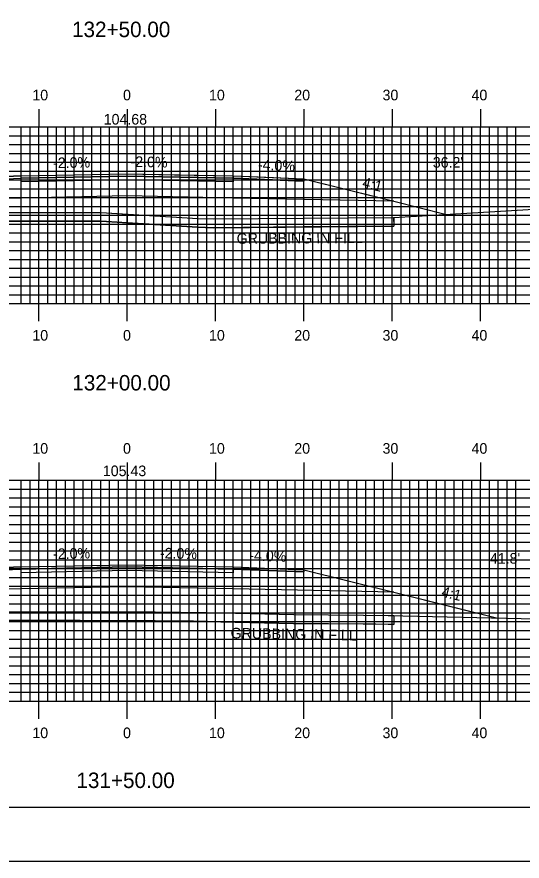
# Model space of a CAD drawing. Extents: x 1774383 to 1774727, y 442591 to 442811.
# Drawn here: x 1774536.7 to 1774593.9, y 442590.5 to 442686.1 of the extents above; entities that cross this region are included whole.
import ezdxf

# ---------------------------------------------------------------- set-up
doc = ezdxf.new("R2010")
doc.units = 0
for name, color, linetype in [('ANNOTATION', 7, 'Continuous'), ('BORDER', 7, 'Continuous'), ('D_Roadway_Centerline', 7, 'Continuous'), ('D_Roadway_Centerline_Text', 7, 'Continuous'), ('D_Roadway_Edge_Shoulder', 7, 'Continuous'), ('D_Roadway_Edge_TW', 7, 'Continuous'), ('D_Roadway_Pavement', 7, 'Continuous'), ('D_Roadway_SlopeLines', 7, 'Continuous'), ('D_Roadway_SubGrade', 7, 'Continuous'), ('D_Text_Standard', 7, 'Continuous'), ('GRUBBING IN FILL', 7, 'Continuous'), ('H_V ANNOTATION', 7, 'Continuous'), ('MAJOR', 7, 'Continuous'), ('MINOR', 7, 'Continuous'), ('PLOT BOUNDARY', 7, 'Continuous'), ('S_Roadway_Centerline', 7, 'Continuous')]:
    doc.layers.add(name, color=color, linetype=linetype)

msp = doc.modelspace()

# ---------------------------------------------------------------- linework, layer by layer
at = {"layer": 'BORDER'}
msp.add_lwpolyline([(1774399.572, 442596.665), (1774719.572, 442596.665), (1774719.572, 442806.665), (1774399.572, 442806.665)], close=True, dxfattribs=at)
at = {"layer": 'D_Roadway_Centerline'}
for points in [[(1774512.297, 442663.565), (1774517.172, 442664.784), (1774517.278, 442664.811), (1774518.998, 442665.24), (1774523.443, 442666.352), (1774529.172, 442667.784), (1774537.172, 442668.104), (1774549.172, 442668.344), (1774554.507, 442668.238), (1774561.172, 442668.104), (1774563.119, 442668.026), (1774569.172, 442667.784), (1774577.691, 442665.654), (1774579.346, 442665.24), (1774585.327, 442663.745)], [(1774511.278, 442619.06), (1774517.172, 442620.534), (1774517.836, 442620.7), (1774518.998, 442620.99), (1774522.93, 442621.973), (1774529.172, 442623.534), (1774537.172, 442623.854), (1774549.172, 442624.094), (1774561.173, 442623.854), (1774569.172, 442623.534), (1774579.346, 442620.99), (1774585.953, 442619.339), (1774590.971, 442618.084)]]:
    msp.add_lwpolyline(points, dxfattribs=at)
at = {"layer": 'D_Roadway_Edge_Shoulder'}
for points in [[(1774537.172, 442668.104), (1774529.172, 442667.784), (1774529.172, 442667.534), (1774537.172, 442667.854)], [(1774561.172, 442668.104), (1774569.172, 442667.784), (1774569.172, 442667.534), (1774561.172, 442667.854)], [(1774537.172, 442623.854), (1774529.172, 442623.534), (1774529.172, 442623.284), (1774537.172, 442623.604)], [(1774561.173, 442623.854), (1774569.172, 442623.534), (1774569.172, 442623.284), (1774561.173, 442623.604)]]:
    msp.add_lwpolyline(points, close=True, dxfattribs=at)
at = {"layer": 'D_Roadway_Edge_TW'}
for points in [[(1774537.172, 442667.854), (1774537.172, 442668.104), (1774549.172, 442668.344), (1774561.172, 442668.104), (1774561.172, 442667.854), (1774549.172, 442668.094)], [(1774537.172, 442623.604), (1774537.172, 442623.854), (1774549.172, 442624.094), (1774561.173, 442623.854), (1774561.173, 442623.604), (1774549.172, 442623.844)]]:
    msp.add_lwpolyline(points, close=True, dxfattribs=at)
at = {"layer": 'D_Roadway_Pavement'}
for points in [[(1774537.172, 442667.437), (1774537.172, 442667.854), (1774549.172, 442668.094), (1774561.172, 442667.854), (1774561.172, 442667.437), (1774549.172, 442667.677)], [(1774537.172, 442623.187), (1774537.172, 442623.604), (1774549.172, 442623.844), (1774561.173, 442623.604), (1774561.173, 442623.187), (1774549.172, 442623.427)]]:
    msp.add_lwpolyline(points, close=True, dxfattribs=at)
at = {"layer": 'D_Roadway_SlopeLines'}
for points in [[(1774569.172, 442667.784), (1774579.346, 442665.24), (1774585.327, 442663.745)], [(1774569.172, 442623.534), (1774579.346, 442620.99), (1774590.971, 442618.084)]]:
    msp.add_lwpolyline(points, dxfattribs=at)
at = {"layer": 'D_Roadway_SubGrade'}
for points in [[(1774537.172, 442665.604), (1774518.998, 442665.24), (1774529.172, 442667.784), (1774529.172, 442667.534), (1774537.172, 442667.854), (1774549.172, 442668.094), (1774561.172, 442667.854), (1774569.172, 442667.534), (1774569.172, 442667.784), (1774579.346, 442665.24), (1774561.172, 442665.604), (1774549.172, 442665.844)], [(1774537.172, 442621.354), (1774518.998, 442620.99), (1774529.172, 442623.534), (1774529.172, 442623.284), (1774537.172, 442623.604), (1774549.172, 442623.844), (1774561.173, 442623.604), (1774569.172, 442623.284), (1774569.172, 442623.534), (1774579.346, 442620.99), (1774561.173, 442621.354), (1774549.172, 442621.594)]]:
    msp.add_lwpolyline(points, close=True, dxfattribs=at)
at = {"layer": 'GRUBBING IN FILL'}
for p, q in [((1774579.346, 442663.423), (1774579.346, 442662.421)), ((1774579.346, 442663.423), (1774579.346, 442662.421)), ((1774579.346, 442618.349), (1774579.346, 442617.348)), ((1774579.346, 442618.349), (1774579.346, 442617.348))]:
    msp.add_line(p, q, dxfattribs=at)
for points in [[(1774518.998, 442663.701), (1774522.021, 442663.762), (1774532.978, 442663.985), (1774539.889, 442663.982), (1774546.228, 442663.979), (1774549.172, 442663.793), (1774549.172, 442662.791), (1774546.196, 442662.979), (1774539.876, 442662.982), (1774533.555, 442662.984), (1774525.99, 442662.843), (1774518.998, 442662.701)], [(1774518.998, 442663.701), (1774522.021, 442663.762), (1774532.978, 442663.985), (1774539.889, 442663.982), (1774546.228, 442663.979), (1774549.172, 442663.793), (1774549.172, 442662.791), (1774546.196, 442662.979), (1774539.876, 442662.982), (1774533.555, 442662.984), (1774525.99, 442662.843), (1774518.998, 442662.701)], [(1774549.172, 442663.793), (1774551.687, 442663.634), (1774557.147, 442663.289), (1774558.926, 442663.249), (1774569.111, 442663.335), (1774579.296, 442663.421), (1774579.346, 442662.421), (1774569.132, 442662.335), (1774558.919, 442662.249), (1774557.104, 442662.29), (1774551.65, 442662.635), (1774549.172, 442662.791)], [(1774549.172, 442663.793), (1774551.687, 442663.634), (1774557.147, 442663.289), (1774558.926, 442663.249), (1774569.111, 442663.335), (1774579.296, 442663.421), (1774579.346, 442662.421), (1774569.132, 442662.335), (1774558.919, 442662.249), (1774557.104, 442662.29), (1774551.65, 442662.635), (1774549.172, 442662.791)], [(1774518.998, 442619.027), (1774521.621, 442618.997), (1774530.184, 442618.901), (1774535.375, 442618.788), (1774543.86, 442618.773), (1774549.172, 442618.764), (1774549.172, 442617.764), (1774543.852, 442617.773), (1774535.364, 442617.788), (1774530.168, 442617.901), (1774524.583, 442617.964), (1774518.998, 442618.026)], [(1774518.998, 442619.027), (1774521.621, 442618.997), (1774530.184, 442618.901), (1774535.375, 442618.788), (1774543.86, 442618.773), (1774549.172, 442618.764), (1774549.172, 442617.764), (1774543.852, 442617.773), (1774535.364, 442617.788), (1774530.168, 442617.901), (1774524.583, 442617.964), (1774518.998, 442618.026)], [(1774549.172, 442618.764), (1774552.345, 442618.759), (1774556.689, 442618.702), (1774558.135, 442618.672), (1774563.076, 442618.561), (1774568.018, 442618.449), (1774571.958, 442618.419), (1774575.898, 442618.39), (1774578.717, 442618.363), (1774579.346, 442618.349), (1774579.346, 442617.348), (1774577.295, 442617.376), (1774571.946, 442617.419), (1774568.003, 442617.449), (1774563.058, 442617.561), (1774556.671, 442617.702), (1774552.34, 442617.759), (1774549.172, 442617.764)], [(1774549.172, 442618.764), (1774552.345, 442618.759), (1774556.689, 442618.702), (1774558.135, 442618.672), (1774563.076, 442618.561), (1774568.018, 442618.449), (1774571.958, 442618.419), (1774575.898, 442618.39), (1774578.717, 442618.363), (1774579.346, 442618.349), (1774579.346, 442617.348), (1774577.295, 442617.376), (1774571.946, 442617.419), (1774568.003, 442617.449), (1774563.058, 442617.561), (1774556.671, 442617.702), (1774552.34, 442617.759), (1774549.172, 442617.764)]]:
    msp.add_lwpolyline(points, close=True, dxfattribs=at)
for points in [[(1774518.998, 442662.701), (1774532.981, 442662.985), (1774533.233, 442662.981), (1774533.555, 442662.984), (1774546.196, 442662.979), (1774557.104, 442662.29), (1774558.919, 442662.249), (1774579.346, 442662.421)], [(1774518.998, 442662.701), (1774532.981, 442662.985), (1774533.233, 442662.981), (1774533.555, 442662.984), (1774546.196, 442662.979), (1774557.104, 442662.29), (1774558.919, 442662.249), (1774579.346, 442662.421)], [(1774518.998, 442618.026), (1774530.168, 442617.901), (1774535.364, 442617.788), (1774552.34, 442617.759), (1774555.229, 442617.732), (1774558.114, 442617.672), (1774568.003, 442617.449), (1774575.889, 442617.39), (1774578.7, 442617.363), (1774579.346, 442617.348)], [(1774518.998, 442618.026), (1774530.168, 442617.901), (1774535.364, 442617.788), (1774552.34, 442617.759), (1774555.229, 442617.732), (1774558.114, 442617.672), (1774568.003, 442617.449), (1774575.889, 442617.39), (1774578.7, 442617.363), (1774579.346, 442617.348)]]:
    msp.add_lwpolyline(points, dxfattribs=at)
at = {"layer": 'MAJOR'}
for p, q in [((1774539.172, 442675.669), (1774539.172, 442673.665)), ((1774549.172, 442675.669), (1774549.172, 442673.665)), ((1774559.172, 442675.669), (1774559.172, 442673.665)), ((1774569.172, 442675.669), (1774569.172, 442673.665)), ((1774579.172, 442675.669), (1774579.172, 442673.665)), ((1774589.172, 442675.669), (1774589.172, 442673.665)), ((1774409.172, 442673.665), (1774689.172, 442673.665)), ((1774409.172, 442673.665), (1774689.172, 442673.665)), ((1774539.172, 442653.665), (1774539.172, 442673.665)), ((1774549.172, 442653.665), (1774549.172, 442673.665)), ((1774559.172, 442653.665), (1774559.172, 442673.665)), ((1774569.172, 442653.665), (1774569.172, 442673.665)), ((1774579.172, 442653.665), (1774579.172, 442673.665)), ((1774589.172, 442653.665), (1774589.172, 442673.665)), ((1774409.172, 442668.665), (1774689.172, 442668.665)), ((1774409.172, 442663.665), (1774689.172, 442663.665)), ((1774409.172, 442658.665), (1774689.172, 442658.665)), ((1774409.172, 442653.665), (1774689.172, 442653.665)), ((1774409.172, 442653.665), (1774689.172, 442653.665)), ((1774539.172, 442651.661), (1774539.172, 442653.665)), ((1774549.172, 442651.661), (1774549.172, 442653.665)), ((1774559.172, 442651.661), (1774559.172, 442653.665)), ((1774569.172, 442651.661), (1774569.172, 442653.665)), ((1774579.172, 442651.661), (1774579.172, 442653.665)), ((1774589.172, 442651.661), (1774589.172, 442653.665)), ((1774539.172, 442635.669), (1774539.172, 442633.665)), ((1774549.172, 442635.669), (1774549.172, 442633.665)), ((1774559.172, 442635.669), (1774559.172, 442633.665)), ((1774569.172, 442635.669), (1774569.172, 442633.665)), ((1774579.172, 442635.669), (1774579.172, 442633.665)), ((1774589.172, 442635.669), (1774589.172, 442633.665)), ((1774409.172, 442633.665), (1774689.172, 442633.665)), ((1774409.172, 442633.665), (1774689.172, 442633.665)), ((1774539.172, 442608.665), (1774539.172, 442633.665)), ((1774549.172, 442608.665), (1774549.172, 442633.665)), ((1774559.172, 442608.665), (1774559.172, 442633.665)), ((1774569.172, 442608.665), (1774569.172, 442633.665)), ((1774579.172, 442608.665), (1774579.172, 442633.665)), ((1774589.172, 442608.665), (1774589.172, 442633.665)), ((1774409.172, 442628.665), (1774689.172, 442628.665)), ((1774409.172, 442623.665), (1774689.172, 442623.665)), ((1774409.172, 442618.665), (1774689.172, 442618.665)), ((1774409.172, 442613.665), (1774689.172, 442613.665)), ((1774409.172, 442608.665), (1774689.172, 442608.665)), ((1774409.172, 442608.665), (1774689.172, 442608.665)), ((1774539.172, 442606.661), (1774539.172, 442608.665)), ((1774549.172, 442606.661), (1774549.172, 442608.665)), ((1774559.172, 442606.661), (1774559.172, 442608.665)), ((1774569.172, 442606.661), (1774569.172, 442608.665)), ((1774579.172, 442606.661), (1774579.172, 442608.665)), ((1774589.172, 442606.661), (1774589.172, 442608.665))]:
    msp.add_line(p, q, dxfattribs=at)
at = {"layer": 'MINOR'}
for p, q in [((1774537.172, 442653.665), (1774537.172, 442673.665)), ((1774538.172, 442653.665), (1774538.172, 442673.665)), ((1774540.172, 442653.665), (1774540.172, 442673.665)), ((1774541.172, 442653.665), (1774541.172, 442673.665)), ((1774542.172, 442653.665), (1774542.172, 442673.665)), ((1774543.172, 442653.665), (1774543.172, 442673.665)), ((1774544.172, 442653.665), (1774544.172, 442673.665)), ((1774545.172, 442653.665), (1774545.172, 442673.665)), ((1774546.172, 442653.665), (1774546.172, 442673.665)), ((1774547.172, 442653.665), (1774547.172, 442673.665)), ((1774548.172, 442653.665), (1774548.172, 442673.665)), ((1774550.172, 442653.665), (1774550.172, 442673.665)), ((1774551.172, 442653.665), (1774551.172, 442673.665)), ((1774552.172, 442653.665), (1774552.172, 442673.665)), ((1774553.172, 442653.665), (1774553.172, 442673.665)), ((1774554.172, 442653.665), (1774554.172, 442673.665)), ((1774555.172, 442653.665), (1774555.172, 442673.665)), ((1774556.172, 442653.665), (1774556.172, 442673.665)), ((1774557.172, 442653.665), (1774557.172, 442673.665)), ((1774558.172, 442653.665), (1774558.172, 442673.665)), ((1774560.172, 442653.665), (1774560.172, 442673.665)), ((1774561.172, 442653.665), (1774561.172, 442673.665)), ((1774562.172, 442653.665), (1774562.172, 442673.665)), ((1774563.172, 442653.665), (1774563.172, 442673.665)), ((1774564.172, 442653.665), (1774564.172, 442673.665)), ((1774565.172, 442653.665), (1774565.172, 442673.665)), ((1774566.172, 442653.665), (1774566.172, 442673.665)), ((1774567.172, 442653.665), (1774567.172, 442673.665)), ((1774568.172, 442653.665), (1774568.172, 442673.665)), ((1774570.172, 442653.665), (1774570.172, 442673.665)), ((1774571.172, 442653.665), (1774571.172, 442673.665)), ((1774572.172, 442653.665), (1774572.172, 442673.665)), ((1774573.172, 442653.665), (1774573.172, 442673.665)), ((1774574.172, 442653.665), (1774574.172, 442673.665)), ((1774575.172, 442653.665), (1774575.172, 442673.665)), ((1774576.172, 442653.665), (1774576.172, 442673.665)), ((1774577.172, 442653.665), (1774577.172, 442673.665)), ((1774578.172, 442653.665), (1774578.172, 442673.665)), ((1774580.172, 442653.665), (1774580.172, 442673.665)), ((1774581.172, 442653.665), (1774581.172, 442673.665)), ((1774582.172, 442653.665), (1774582.172, 442673.665)), ((1774583.172, 442653.665), (1774583.172, 442673.665)), ((1774584.172, 442653.665), (1774584.172, 442673.665)), ((1774585.172, 442653.665), (1774585.172, 442673.665)), ((1774586.172, 442653.665), (1774586.172, 442673.665)), ((1774587.172, 442653.665), (1774587.172, 442673.665)), ((1774588.172, 442653.665), (1774588.172, 442673.665)), ((1774590.172, 442653.665), (1774590.172, 442673.665)), ((1774591.172, 442653.665), (1774591.172, 442673.665)), ((1774592.172, 442653.665), (1774592.172, 442673.665)), ((1774593.172, 442653.665), (1774593.172, 442673.665)), ((1774409.172, 442672.665), (1774689.172, 442672.665)), ((1774409.172, 442671.665), (1774689.172, 442671.665)), ((1774409.172, 442670.665), (1774689.172, 442670.665)), ((1774409.172, 442669.665), (1774689.172, 442669.665)), ((1774409.172, 442667.665), (1774689.172, 442667.665)), ((1774409.172, 442666.665), (1774689.172, 442666.665)), ((1774409.172, 442665.665), (1774689.172, 442665.665)), ((1774409.172, 442664.665), (1774689.172, 442664.665)), ((1774409.172, 442662.665), (1774689.172, 442662.665)), ((1774409.172, 442661.665), (1774689.172, 442661.665)), ((1774409.172, 442660.665), (1774689.172, 442660.665)), ((1774409.172, 442659.665), (1774689.172, 442659.665)), ((1774409.172, 442657.665), (1774689.172, 442657.665)), ((1774409.172, 442656.665), (1774689.172, 442656.665)), ((1774409.172, 442655.665), (1774689.172, 442655.665)), ((1774409.172, 442654.665), (1774689.172, 442654.665)), ((1774537.172, 442608.665), (1774537.172, 442633.665)), ((1774538.172, 442608.665), (1774538.172, 442633.665)), ((1774540.172, 442608.665), (1774540.172, 442633.665)), ((1774541.172, 442608.665), (1774541.172, 442633.665)), ((1774542.172, 442608.665), (1774542.172, 442633.665)), ((1774543.172, 442608.665), (1774543.172, 442633.665)), ((1774544.172, 442608.665), (1774544.172, 442633.665)), ((1774545.172, 442608.665), (1774545.172, 442633.665)), ((1774546.172, 442608.665), (1774546.172, 442633.665)), ((1774547.172, 442608.665), (1774547.172, 442633.665)), ((1774548.172, 442608.665), (1774548.172, 442633.665)), ((1774550.172, 442608.665), (1774550.172, 442633.665)), ((1774551.172, 442608.665), (1774551.172, 442633.665)), ((1774552.172, 442608.665), (1774552.172, 442633.665)), ((1774553.172, 442608.665), (1774553.172, 442633.665)), ((1774554.172, 442608.665), (1774554.172, 442633.665)), ((1774555.172, 442608.665), (1774555.172, 442633.665)), ((1774556.172, 442608.665), (1774556.172, 442633.665)), ((1774557.172, 442608.665), (1774557.172, 442633.665)), ((1774558.172, 442608.665), (1774558.172, 442633.665)), ((1774560.172, 442608.665), (1774560.172, 442633.665)), ((1774561.172, 442608.665), (1774561.172, 442633.665)), ((1774562.172, 442608.665), (1774562.172, 442633.665)), ((1774563.172, 442608.665), (1774563.172, 442633.665)), ((1774564.172, 442608.665), (1774564.172, 442633.665)), ((1774565.172, 442608.665), (1774565.172, 442633.665)), ((1774566.172, 442608.665), (1774566.172, 442633.665)), ((1774567.172, 442608.665), (1774567.172, 442633.665)), ((1774568.172, 442608.665), (1774568.172, 442633.665)), ((1774570.172, 442608.665), (1774570.172, 442633.665)), ((1774571.172, 442608.665), (1774571.172, 442633.665)), ((1774572.172, 442608.665), (1774572.172, 442633.665)), ((1774573.172, 442608.665), (1774573.172, 442633.665)), ((1774574.172, 442608.665), (1774574.172, 442633.665)), ((1774575.172, 442608.665), (1774575.172, 442633.665)), ((1774576.172, 442608.665), (1774576.172, 442633.665)), ((1774577.172, 442608.665), (1774577.172, 442633.665)), ((1774578.172, 442608.665), (1774578.172, 442633.665)), ((1774580.172, 442608.665), (1774580.172, 442633.665)), ((1774581.172, 442608.665), (1774581.172, 442633.665)), ((1774582.172, 442608.665), (1774582.172, 442633.665)), ((1774583.172, 442608.665), (1774583.172, 442633.665)), ((1774584.172, 442608.665), (1774584.172, 442633.665)), ((1774585.172, 442608.665), (1774585.172, 442633.665)), ((1774586.172, 442608.665), (1774586.172, 442633.665)), ((1774587.172, 442608.665), (1774587.172, 442633.665)), ((1774588.172, 442608.665), (1774588.172, 442633.665)), ((1774590.172, 442608.665), (1774590.172, 442633.665)), ((1774591.172, 442608.665), (1774591.172, 442633.665)), ((1774592.172, 442608.665), (1774592.172, 442633.665)), ((1774593.172, 442608.665), (1774593.172, 442633.665)), ((1774409.172, 442632.665), (1774689.172, 442632.665)), ((1774409.172, 442631.665), (1774689.172, 442631.665)), ((1774409.172, 442630.665), (1774689.172, 442630.665)), ((1774409.172, 442629.665), (1774689.172, 442629.665)), ((1774409.172, 442627.665), (1774689.172, 442627.665)), ((1774409.172, 442626.665), (1774689.172, 442626.665)), ((1774409.172, 442625.665), (1774689.172, 442625.665)), ((1774409.172, 442624.665), (1774689.172, 442624.665)), ((1774409.172, 442622.665), (1774689.172, 442622.665)), ((1774409.172, 442621.665), (1774689.172, 442621.665)), ((1774409.172, 442620.665), (1774689.172, 442620.665)), ((1774409.172, 442619.665), (1774689.172, 442619.665)), ((1774409.172, 442617.665), (1774689.172, 442617.665)), ((1774409.172, 442616.665), (1774689.172, 442616.665)), ((1774409.172, 442615.665), (1774689.172, 442615.665)), ((1774409.172, 442614.665), (1774689.172, 442614.665)), ((1774409.172, 442612.665), (1774689.172, 442612.665)), ((1774409.172, 442611.665), (1774689.172, 442611.665)), ((1774409.172, 442610.665), (1774689.172, 442610.665)), ((1774409.172, 442609.665), (1774689.172, 442609.665))]:
    msp.add_line(p, q, dxfattribs=at)
at = {"layer": 'PLOT BOUNDARY'}
msp.add_lwpolyline([(1774383.385, 442590.547), (1774723.385, 442590.547), (1774723.385, 442810.547), (1774383.385, 442810.547)], close=True, dxfattribs=at)
at = {"layer": 'S_Roadway_Centerline'}
for points in [[(1774486.701, 442664.161), (1774489.383, 442664.027), (1774498.897, 442663.651), (1774509.835, 442663.514), (1774510.506, 442663.506), (1774511.065, 442663.54), (1774532.978, 442663.985), (1774533.237, 442663.981), (1774533.551, 442663.984), (1774546.228, 442663.979), (1774557.147, 442663.289), (1774558.926, 442663.249), (1774579.296, 442663.421), (1774581.926, 442663.541), (1774601.548, 442664.721)], [(1774409.172, 442620.913), (1774409.418, 442620.916), (1774422.837, 442621.32), (1774428.202, 442621.497), (1774433.877, 442621.526), (1774445.557, 442621.32), (1774451.225, 442621.215), (1774468.104, 442620.333), (1774474.637, 442620.193), (1774481.884, 442619.911), (1774486.894, 442619.928), (1774491.126, 442619.822), (1774505.753, 442619.321), (1774509.5, 442619.027), (1774513.058, 442619.093), (1774530.184, 442618.901), (1774535.375, 442618.788), (1774552.345, 442618.759), (1774555.244, 442618.732), (1774558.135, 442618.672), (1774568.018, 442618.449), (1774575.898, 442618.39), (1774578.717, 442618.363), (1774600.441, 442617.868)]]:
    msp.add_lwpolyline(points, dxfattribs=at)

# ---------------------------------------------------------------- texts
at = {"layer": 'ANNOTATION'}
for s, rotation, p in [('-2.0%', 1.14582, (1774540.778, 442668.977)), ('-2.0%', 358.85431, (1774549.525, 442669.138)), ('-4.0%', 357.70927, (1774563.937, 442668.795)), ('4:1', 345.96084, (1774575.701, 442666.834)), ('-2.0%', 1.14572, (1774540.778, 442624.727)), ('-2.0%', 358.85428, (1774552.858, 442624.821)), ('-4.0%', 357.70914, (1774562.964, 442624.584)), ('4:1', 345.9656, (1774584.664, 442620.522))]:
    msp.add_text(s, height=1.2, rotation=rotation, dxfattribs=at).set_placement(p)
at = {"layer": 'D_Roadway_Centerline'}
for s, p in [('C', (1774549.166, 442668.344)), ('L', (1774549.172, 442668.337)), ('C', (1774549.167, 442624.094)), ('L', (1774549.172, 442624.087))]:
    msp.add_text(s, height=0.0146, dxfattribs=at).set_placement(p)
at = {"layer": 'D_Roadway_Centerline_Text'}
for s, p in [('104.68', (1774546.502, 442673.924)), ('105.43', (1774546.406, 442634.124))]:
    msp.add_text(s, height=1.2, dxfattribs=at).set_placement(p)
at = {"layer": 'D_Text_Standard'}
for s, p in [("36.2'", (1774583.755, 442669.048)), ("41.8'", (1774590.217, 442624.217))]:
    msp.add_text(s, height=1.2, dxfattribs=at).set_placement(p)
at = {"layer": 'GRUBBING IN FILL'}
for rotation, p in [(0.33301, (1774561.555, 442660.425)), (358.9728, (1774560.866, 442615.767))]:
    msp.add_text('GRUBBING IN FILL', height=1.2, rotation=rotation, dxfattribs=at).set_placement(p)
at = {"layer": 'H_V ANNOTATION'}
for s, height, p in [('132+50.00', 1.75, (1774542.914, 442683.821)), ('10', 1.2, (1774538.423, 442676.665)), ('0', 1.2, (1774548.69, 442676.665)), ('10', 1.2, (1774558.423, 442676.665)), ('20', 1.2, (1774568.08, 442676.665)), ('30', 1.2, (1774578.069, 442676.665)), ('40', 1.2, (1774588.144, 442676.665)), ('10', 1.2, (1774538.423, 442649.465)), ('0', 1.2, (1774548.69, 442649.465)), ('10', 1.2, (1774558.423, 442649.465)), ('20', 1.2, (1774568.08, 442649.465)), ('30', 1.2, (1774578.069, 442649.465)), ('40', 1.2, (1774588.144, 442649.465)), ('132+00.00', 1.75, (1774542.945, 442643.821)), ('10', 1.2, (1774538.423, 442636.665)), ('0', 1.2, (1774548.69, 442636.665)), ('10', 1.2, (1774558.423, 442636.665)), ('20', 1.2, (1774568.08, 442636.665)), ('30', 1.2, (1774578.069, 442636.665)), ('40', 1.2, (1774588.144, 442636.665)), ('10', 1.2, (1774538.423, 442604.465)), ('0', 1.2, (1774548.69, 442604.465)), ('10', 1.2, (1774558.423, 442604.465)), ('20', 1.2, (1774568.08, 442604.465)), ('30', 1.2, (1774578.069, 442604.465)), ('40', 1.2, (1774588.144, 442604.465)), ('131+50.00', 1.75, (1774543.414, 442598.821))]:
    msp.add_text(s, height=height, dxfattribs=at).set_placement(p)

doc.saveas('drawing.dxf')
